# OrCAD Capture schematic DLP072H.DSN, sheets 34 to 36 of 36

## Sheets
34 PAGE13 - Controller VIDEO I/F: size A3
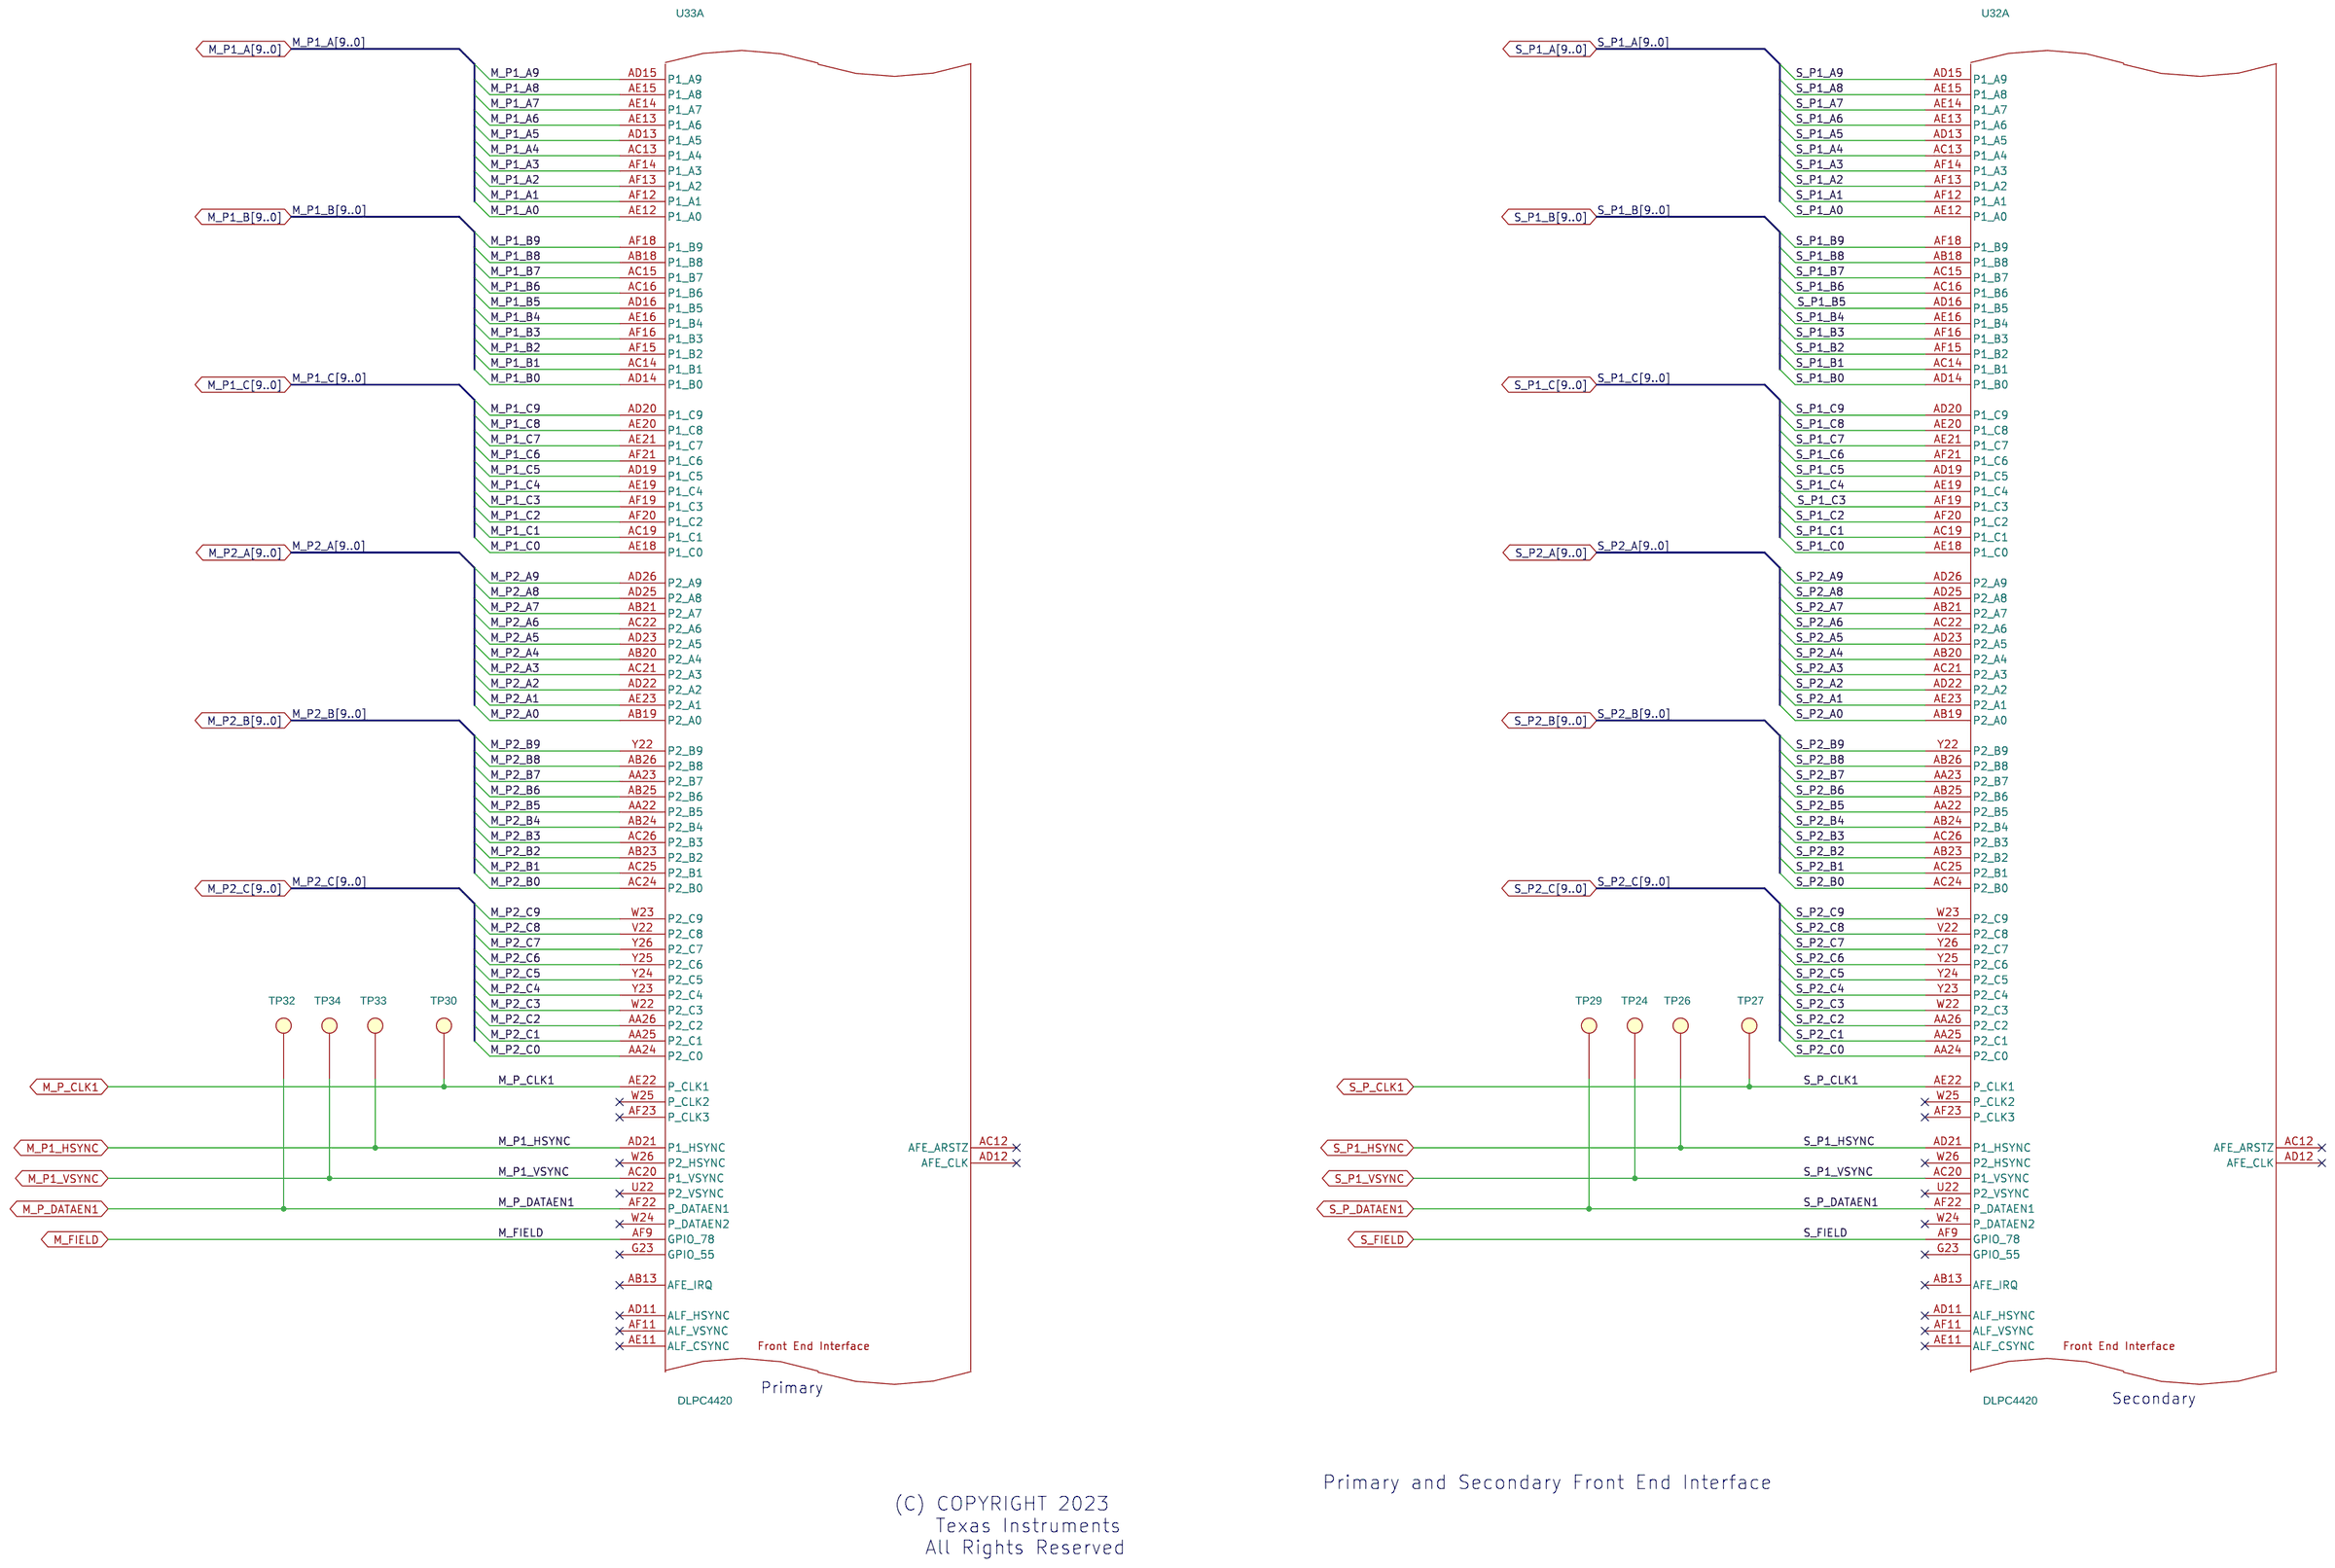
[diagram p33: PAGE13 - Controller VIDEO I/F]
35 PAGE22 - GPIOX, KEYPD I/F, IR: size A3
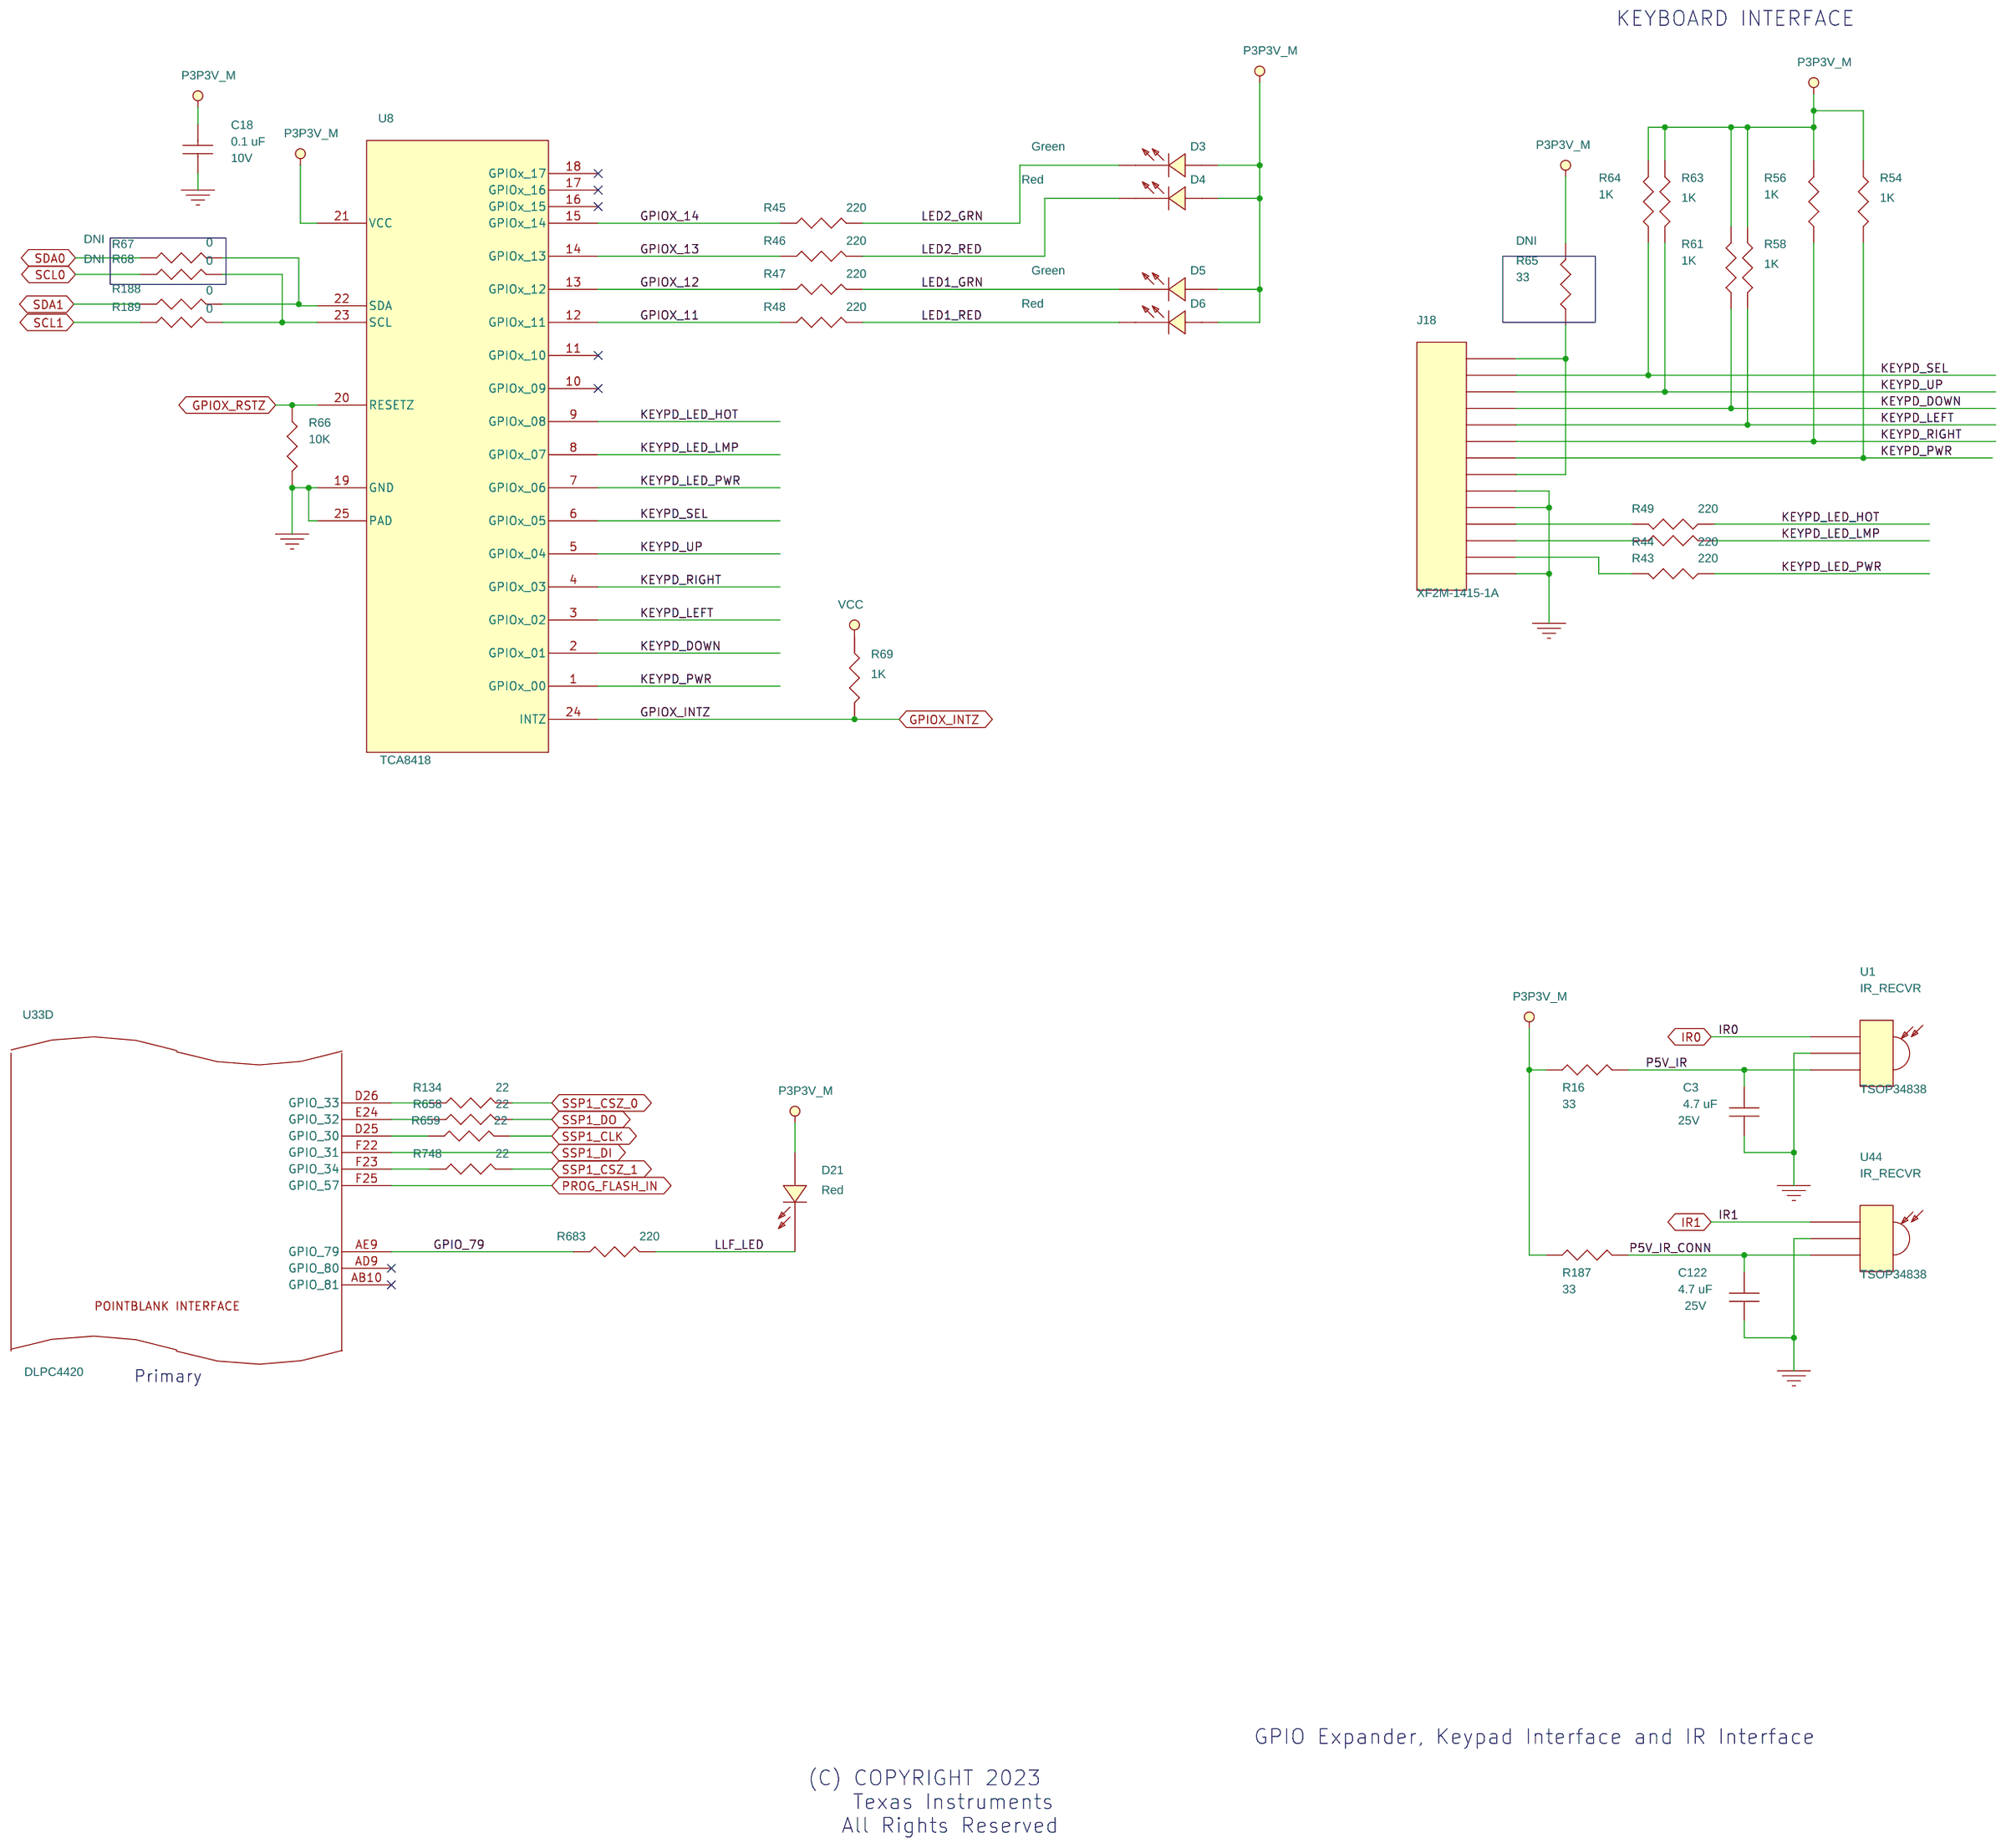
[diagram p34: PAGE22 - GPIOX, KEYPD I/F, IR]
36 PAGE15 - SECONDARY DMD FLEX I/F: size A3
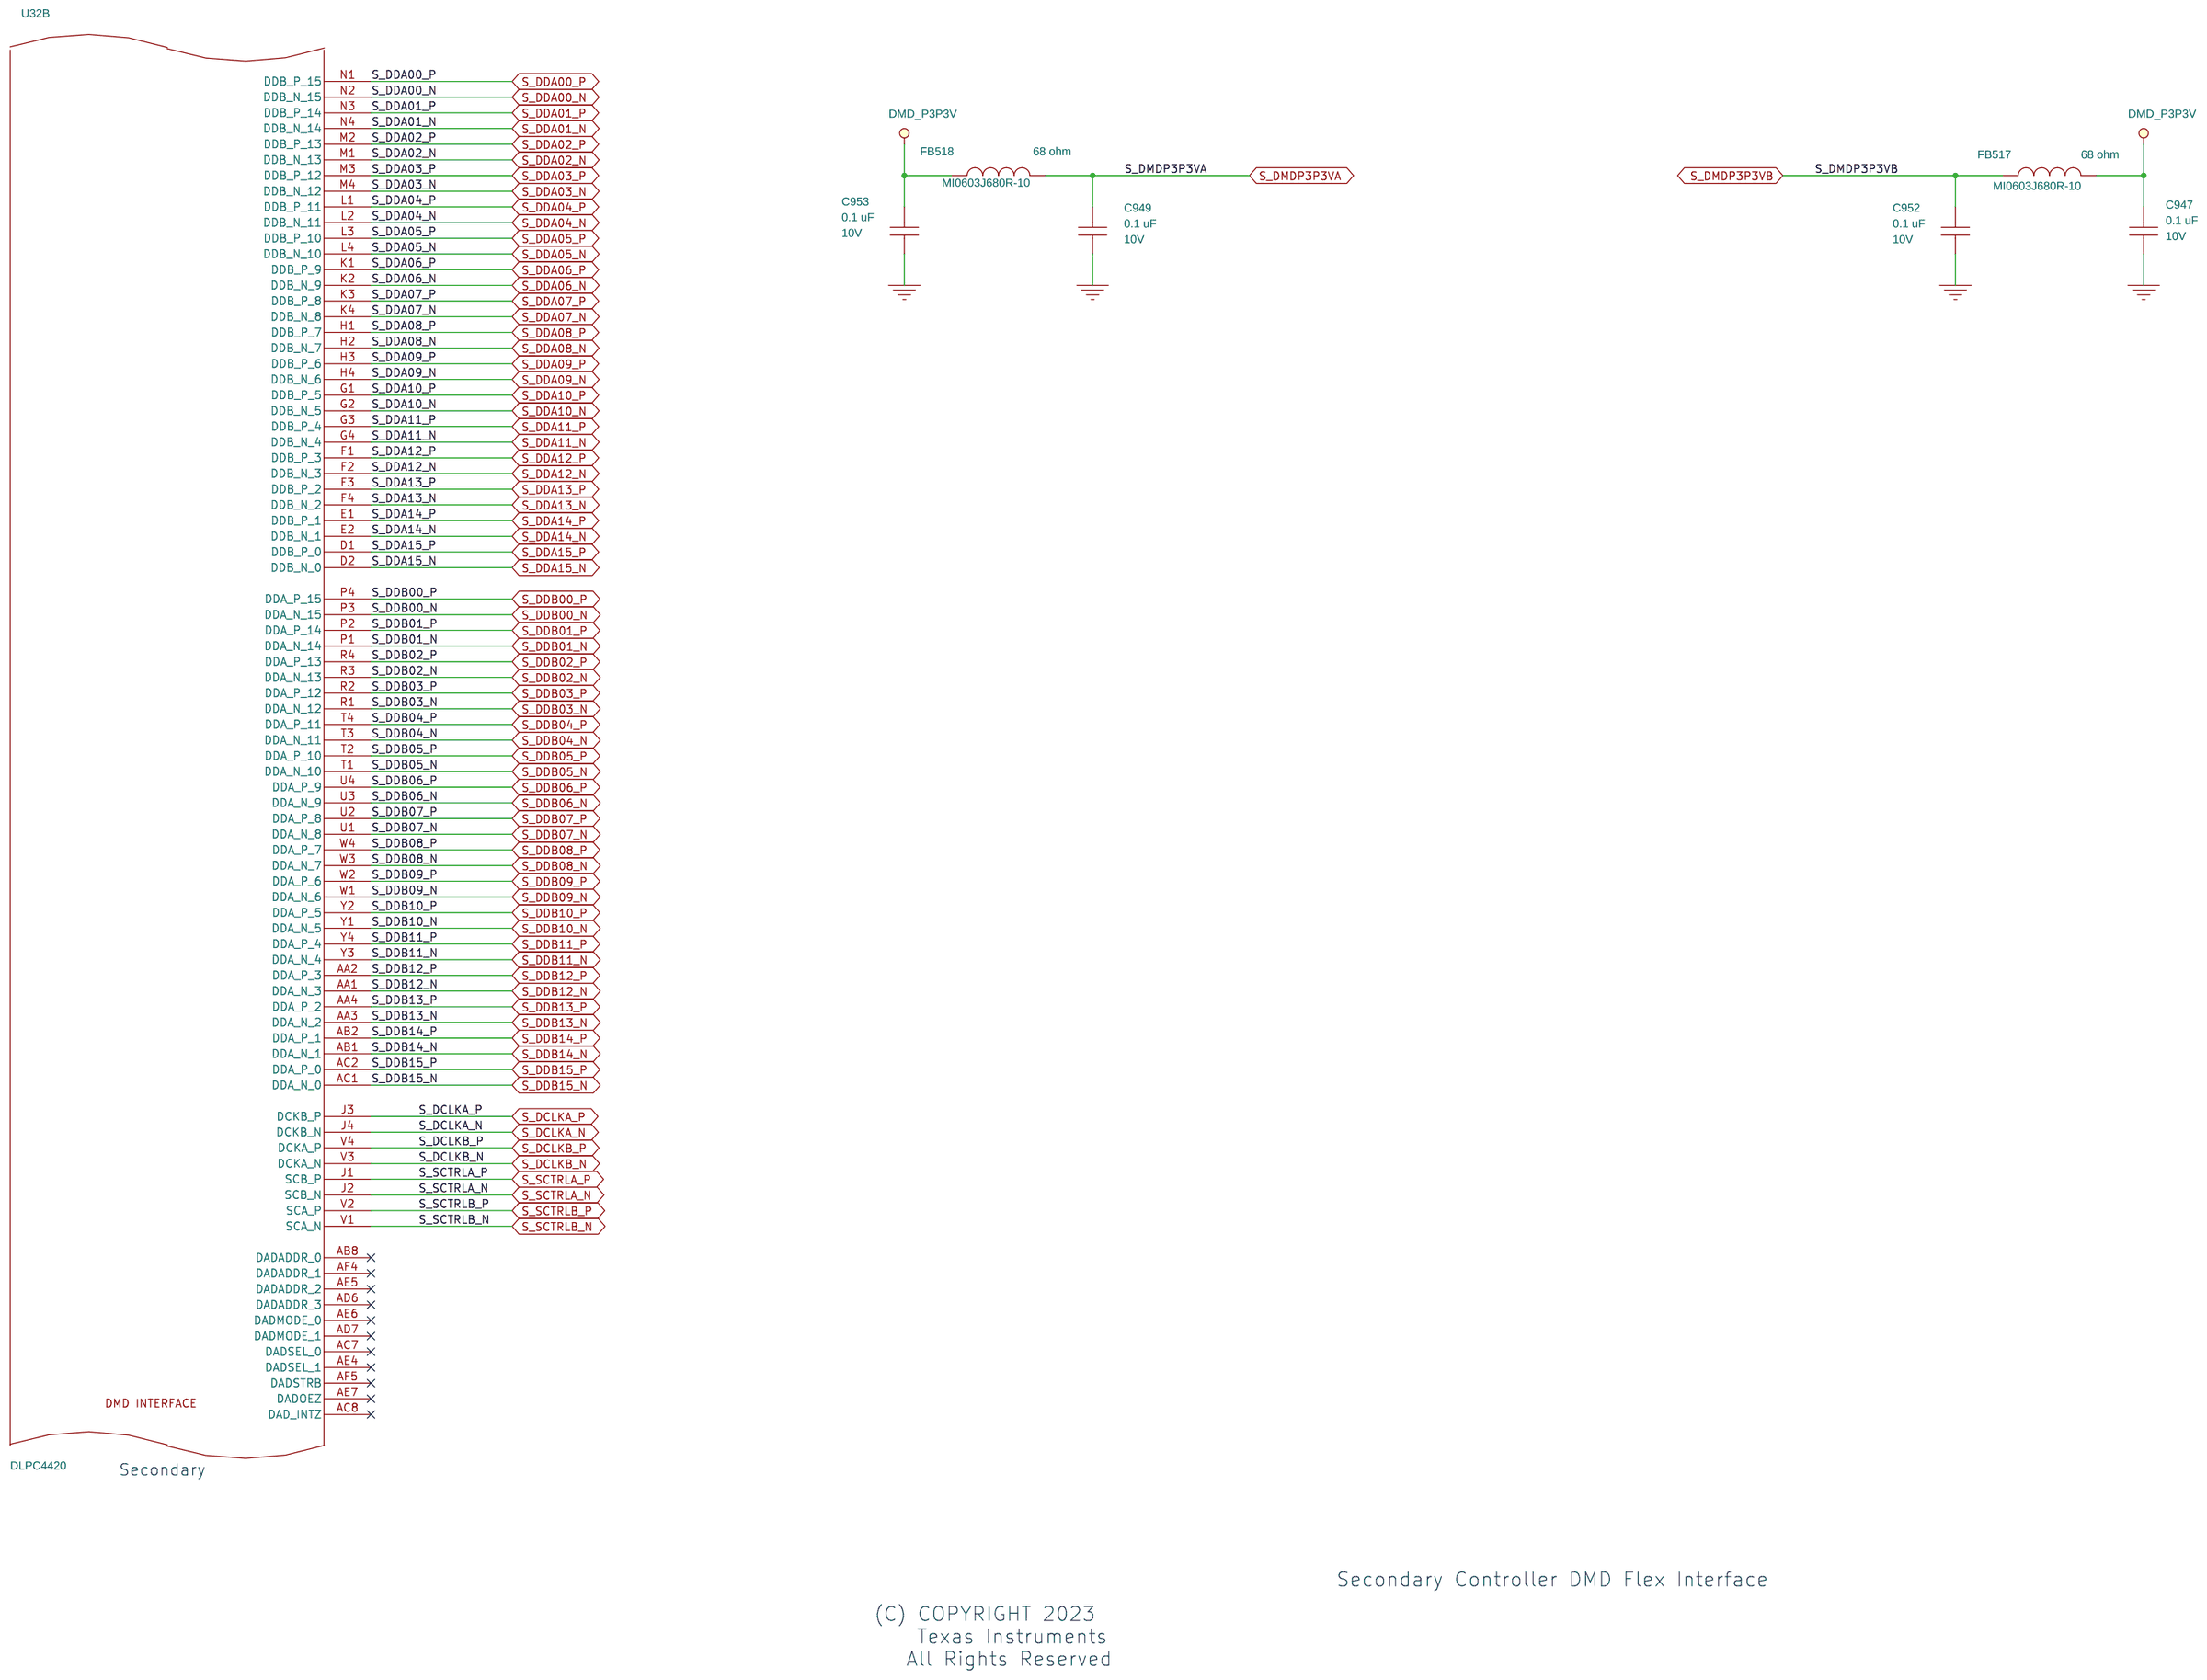
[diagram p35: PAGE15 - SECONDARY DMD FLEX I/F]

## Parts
sheet PAGE13 - Controller VIDEO I/F
TP24  Testpoint  [TP]
TP26  Testpoint  [TP]
TP27  Testpoint  [TP]
TP29  Testpoint  [TP]
TP30  Testpoint  [TP]
TP32  Testpoint  [TP]
TP33  Testpoint  [TP]
TP34  Testpoint  [TP]
sheet PAGE15 - SECONDARY DMD FLEX I/F
C947  0.1 uF  [CAP_0402]
C949  0.1 uF  [CAP_0402]
C952  0.1 uF  [CAP_0402]
C953  0.1 uF  [CAP_0402]
FB517  68 ohm  [FLTR_0603]
FB518  68 ohm  [FLTR_0603]
sheet PAGE16 - INPUT PWR & PMD1000
U32  DLPC4420  [BGA552-DDP4422_TI]  (sections A,B,C,D,E,F,G,H,I,J)
U33  DLPC4420  [BGA552-DDP4422_TI]  (sections A,B,C,D,E,F,G,H,I,J)
sheet PAGE22 - GPIOX, KEYPD I/F, IR
C3  4.7 uF  [CAP_0805]
C18  0.1 uF  [CAP_0402]
C122  4.7 uF  [CAP_0805]
D3  Green  [D_0603]
D4  Red  [D_0603]
D5  Green  [D_0603]
D6  Red  [D_0603]
D21  Red  [D_0603]
J18  CON14  [CONN14-XF2M_OMRON]
R16  33  [RES_0402]
R43  220  [RES_0603]
R44  220  [RES_0603]
R45  220  [RES_0603]
R46  220  [RES_0603]
R47  220  [RES_0603]
R48  220  [RES_0603]
R49  220  [RES_0603]
R54  1K  [RES_0402]
R56  1K  [RES_0402]
R58  1K  [RES_0402]
R61  1K  [RES_0402]
R63  1K  [RES_0402]
R64  1K  [RES_0402]
R65  33  [RES_0402]
R66  10K  [RES_0402]
R67  0  [RES_0402]
R68  0  [RES_0402]
R69  1K  [RES_0402]
R134  22  [RES_0402]
R187  33  [RES_0402]
R188  0  [RES_0402]
R189  0  [RES_0402]
R658  22  [RES_0402]
R659  22  [RES_0402]
R683  220  [RES_0603]
R748  22  [RES_0402]
U1  IR_RECVR  [VISHAY_IR_TSOP348]
U8  TCA8418  [24QFN_TI]
U44  IR_RECVR  [VISHAY_IR_TSOP348]

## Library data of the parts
TP24 TP26 TP27 TP29 TP30 TP32-TP34 = Testpoint: Test point
C18 C947 C949 C952 C953 = CAP_NP: Capacitor; CCA: 34; MFG: KEMET; Part Number: C0402C104K8RACTU; RATING: 10V; SOURCE: DIGI 399-3520-1-ND; TOLERANCE: 10%; Type: X7R
FB517 FB518 = INDUCTOR: Ferrite; CCA: 132; ICA_MFR_NAME: STEWARD; ICA_PARTNUM: $$731362$$MI0603J680R-10; MFG: STEWARD; Part Number: MI0603J680R-10; RATING: 1A, 100MHz; SOURCE: DIGI 240-2372-1-ND
U32 U33 = DDP442x: IC, ASIC; CCA: 54; MFG: TI; Part Number: DLPC4420ZPC; SOURCE: PROVIDED BY TI
C3 C122 = CAP_NP: Capacitor; CCA: 42; MFG: TDK; Part Number: C2012X7R1E475K125AB; RATING: 25V; SOURCE: DIGI 445-5972-1-ND; TOLERANCE: 10%; Type: X7R
D3 D5 = LED_GREEN_CLEAR_0603: LED; Part Number: LTST-C190GKT
D4 D6 D21 = LED_GREEN_CLEAR_0603: LED; MFG Part Number: LTST-C191KRKT; Part Number: LTST-C191KRKT
J18 = CON14: Connector, 14 pin, ribbon; CCA: 177; MFG: OMRON; Part Number: XF2M-1415-1A; SOURCE: DIGI OR755CT-ND
R16 R187 = R: Resistor; CCA: 67; ICA_MFR_NAME: PANASONIC; ICA_PARTNUM: $$1785048$$ERJ-3GSYJ102; MFG: PANASONIC; Part Number: ERJ-2GEJ330X; RATING: 1/10W; SOURCE: DIGI P33JCT-ND; TOLERANCE: 5%
R43-R49 R683 = R: Resistor; CCA: 95; ICA_MFR_NAME: PANASONIC; ICA_PARTNUM: $$1785048$$ERJ-3GSYJ102; MFG: PANASONIC; Part Number: ERJ-3GEYJ221V; RATING: 1/10W; SOURCE: DIGI P220GCT-ND; TOLERANCE: 5%
R54 R56 R58 R61 R63 R64 R69 = R: Resistor; CCA: 64; ICA_MFR_NAME: PANASONIC; ICA_PARTNUM: $$1785048$$ERJ-3GSYJ102; MFG: PANASONIC; Part Number: ERJ-2GEJ102X; RATING: 1/10W; SOURCE: DIGI P1.0KJCT-ND; TOLERANCE: 5%
R65 = R: Resistor; CCA: 67; DNI: DNI; ICA_MFR_NAME: PANASONIC; ICA_PARTNUM: $$1785048$$ERJ-3GSYJ102; MFG: PANASONIC; Part Number: ERJ-2GEJ330X; RATING: 1/10W; SOURCE: DIGI P33JCT-ND; TOLERANCE: 5%
R66 = R: Resistor; CCA: 65; ICA_MFR_NAME: PANASONIC; ICA_PARTNUM: $$1785048$$ERJ-3GSYJ102; MFG: PANASONIC; Part Number: ERJ-2GEJ103X; RATING: 1/10W; SOURCE: DIGI P10.0KLCT-ND; TOLERANCE: 5%
R67 R68 = R: Resistor; CCA: 62; DNI: DNI; ICA_MFR_NAME: PANASONIC; ICA_PARTNUM: $$1785048$$ERJ-3GSYJ102; MFG: PANASONIC; Part Number: ERJ-2GE0R00X; RATING: 1/10W; SOURCE: DIGI P0.0JCT-ND
R134 R658 R659 R748 = R: Resistor; CCA: 143; MFG: YAGEO; Part Number: RC0402FR-0722RL; RATING: 1/16W; SOURCE: DIGI 311-22.0LRTR-ND; TOLERANCE: 1%
R188 R189 = R: Resistor; CCA: 62; ICA_MFR_NAME: PANASONIC; ICA_PARTNUM: $$1785048$$ERJ-3GSYJ102; MFG: PANASONIC; Part Number: ERJ-2GE0R00X; RATING: 1/10W; SOURCE: DIGI P0.0JCT-ND
U1 U44 = IR_RECVR: IC, IR Receiver; CCA: 175; MFG: VISHAY; Part Number: TSOP34838; SOURCE: VISHAY
U8 = TCA8418_0: IC, GPIO Expander; CCA: 160; MFG: TI; Part Number: TCA8418RTWR; SOURCE: DIGI 296-25223-1-ND

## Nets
GND: C3.1 C18.1 C122.1 C947.1 C949.1 C952.1 C953.1 J18.9 J18.10 J18.14 R66.2 U1.2 U8.19(GND) U8.25(PAD) U44.2 ; also on sheet 2 5 6 7 8 9 10 11 12 13 14 15 16 17 18 19 20 21 22 23 24 25 26 27 28 30 31 32 33
P5V_IR: C3.2 R16.1 U1.3
P5V_IR_CONN: C122.2 R187.1 U44.3
DMD_P3P3V: C947.2 C953.2 FB517.1 FB518.1 ; also on sheet 11 14
GPIO_79: R683.1 U33.AE9(GPIO_79)
GPIOX_11: R48.1 U8.12(GPIOx_11)
GPIOX_12: R47.1 U8.13(GPIOx_12)
GPIOX_13: R46.1 U8.14(GPIOx_13)
GPIOX_14: R45.1 U8.15(GPIOx_14)
GPIOX_INTZ: R69.1 U8.24(INTZ) ; also on sheet 17
GPIOX_RSTZ: R66.1 U8.20(RESETZ) ; also on sheet 17
IR0: U1.1 ; also on sheet 17
IR1: U44.1 ; also on sheet 17
KEYPD_DOWN: J18.4 R61.1 U8.2(GPIOx_01)
KEYPD_LED_HOT: R49.2 U8.9(GPIOx_08)
KEYPD_LED_LMP: R44.2 U8.8(GPIOx_07)
KEYPD_LED_PWR: R43.2 U8.7(GPIOx_06)
KEYPD_LEFT: J18.5 R58.1 U8.3(GPIOx_02)
KEYPD_PWR: J18.7 R54.1 U8.1(GPIOx_00)
KEYPD_RIGHT: J18.6 R56.1 U8.4(GPIOx_03)
KEYPD_SEL: J18.2 R64.1 U8.6(GPIOx_05)
KEYPD_UP: J18.3 R63.1 U8.5(GPIOx_04)
LED1_GRN: D5.1(CATHODE) R47.2
LED1_RED: D6.1(CATHODE) R48.2
LED2_GRN: D3.1(CATHODE) R45.2
LED2_RED: D4.1(CATHODE) R46.2
LLF_LED: D21.1(CATHODE) R683.2
M_FIELD: U33.AF9(GPIO_78) ; also on sheet 31
M_P1_A0: U33.AE12(P1_A0) ; also on sheet 31
M_P1_A1: U33.AF12(P1_A1) ; also on sheet 31
M_P1_A2: U33.AF13(P1_A2) ; also on sheet 31
M_P1_A3: U33.AF14(P1_A3) ; also on sheet 31
M_P1_A4: U33.AC13(P1_A4) ; also on sheet 31
M_P1_A5: U33.AD13(P1_A5) ; also on sheet 31
M_P1_A6: U33.AE13(P1_A6) ; also on sheet 31
M_P1_A7: U33.AE14(P1_A7) ; also on sheet 31
M_P1_A8: U33.AE15(P1_A8) ; also on sheet 31
M_P1_A9: U33.AD15(P1_A9) ; also on sheet 31
M_P1_B0: U33.AD14(P1_B0) ; also on sheet 31
M_P1_B1: U33.AC14(P1_B1) ; also on sheet 31
M_P1_B2: U33.AF15(P1_B2) ; also on sheet 31
M_P1_B3: U33.AF16(P1_B3) ; also on sheet 31
M_P1_B4: U33.AE16(P1_B4) ; also on sheet 31
M_P1_B5: U33.AD16(P1_B5) ; also on sheet 31
M_P1_B6: U33.AC16(P1_B6) ; also on sheet 31
M_P1_B7: U33.AC15(P1_B7) ; also on sheet 31
M_P1_B8: U33.AB18(P1_B8) ; also on sheet 31
M_P1_B9: U33.AF18(P1_B9) ; also on sheet 31
M_P1_C0: U33.AE18(P1_C0) ; also on sheet 31
M_P1_C1: U33.AC19(P1_C1) ; also on sheet 31
M_P1_C2: U33.AF20(P1_C2) ; also on sheet 31
M_P1_C3: U33.AF19(P1_C3) ; also on sheet 31
M_P1_C4: U33.AE19(P1_C4) ; also on sheet 31
M_P1_C5: U33.AD19(P1_C5) ; also on sheet 31
M_P1_C6: U33.AF21(P1_C6) ; also on sheet 31
M_P1_C7: U33.AE21(P1_C7) ; also on sheet 31
M_P1_C8: U33.AE20(P1_C8) ; also on sheet 31
M_P1_C9: U33.AD20(P1_C9) ; also on sheet 31
M_P1_HSYNC: TP33.1 U33.AD21(P1_HSYNC) ; also on sheet 31
M_P1_VSYNC: TP34.1 U33.AC20(P1_VSYNC) ; also on sheet 31
M_P2_A0: U33.AB19(P2_A0) ; also on sheet 31
M_P2_A1: U33.AE23(P2_A1) ; also on sheet 31
M_P2_A2: U33.AD22(P2_A2) ; also on sheet 31
M_P2_A3: U33.AC21(P2_A3) ; also on sheet 31
M_P2_A4: U33.AB20(P2_A4) ; also on sheet 31
M_P2_A5: U33.AD23(P2_A5) ; also on sheet 31
M_P2_A6: U33.AC22(P2_A6) ; also on sheet 31
M_P2_A7: U33.AB21(P2_A7) ; also on sheet 31
M_P2_A8: U33.AD25(P2_A8) ; also on sheet 31
M_P2_A9: U33.AD26(P2_A9) ; also on sheet 31
M_P2_B0: U33.AC24(P2_B0) ; also on sheet 31
M_P2_B1: U33.AC25(P2_B1) ; also on sheet 31
M_P2_B2: U33.AB23(P2_B2) ; also on sheet 31
M_P2_B3: U33.AC26(P2_B3) ; also on sheet 31
M_P2_B4: U33.AB24(P2_B4) ; also on sheet 31
M_P2_B5: U33.AA22(P2_B5) ; also on sheet 31
M_P2_B6: U33.AB25(P2_B6) ; also on sheet 31
M_P2_B7: U33.AA23(P2_B7) ; also on sheet 31
M_P2_B8: U33.AB26(P2_B8) ; also on sheet 31
M_P2_B9: U33.Y22(P2_B9) ; also on sheet 31
M_P2_C0: U33.AA24(P2_C0) ; also on sheet 31
M_P2_C1: U33.AA25(P2_C1) ; also on sheet 31
M_P2_C2: U33.AA26(P2_C2) ; also on sheet 31
M_P2_C3: U33.W22(P2_C3) ; also on sheet 31
M_P2_C4: U33.Y23(P2_C4) ; also on sheet 31
M_P2_C5: U33.Y24(P2_C5) ; also on sheet 31
M_P2_C6: U33.Y25(P2_C6) ; also on sheet 31
M_P2_C7: U33.Y26(P2_C7) ; also on sheet 31
M_P2_C8: U33.V22(P2_C8) ; also on sheet 31
M_P2_C9: U33.W23(P2_C9) ; also on sheet 31
M_P_CLK1: TP30.1 U33.AE22(P_CLK1) ; also on sheet 31
M_P_DATAEN1: TP32.1 U33.AF22(P_DATAEN1) ; also on sheet 31
P3P3V_M: C18.2 D3.2(ANODE) D4.2(ANODE) D5.2(ANODE) D6.2(ANODE) D21.2(ANODE) R16.2 R54.2 R56.2 R58.2 R61.2 R63.2 R64.2 R65.2 R69.2 R187.2 U8.21(VCC) ; also on sheet 12 13 14 15 16 17 18 20 21 23 24 27 30
PROG_FLASH_IN: U33.F25(GPIO_57) ; also on sheet 33
S_DCLKA_N: U32.J4(DCKB_N) ; also on sheet 2
S_DCLKA_P: U32.J3(DCKB_P) ; also on sheet 2
S_DCLKB_N: U32.V3(DCKA_N) ; also on sheet 2
S_DCLKB_P: U32.V4(DCKA_P) ; also on sheet 2
S_DDA00_N: U32.N2(DDB_N_15) ; also on sheet 2
S_DDA00_P: U32.N1(DDB_P_15) ; also on sheet 2
S_DDA01_N: U32.N4(DDB_N_14) ; also on sheet 2
S_DDA01_P: U32.N3(DDB_P_14) ; also on sheet 2
S_DDA02_N: U32.M1(DDB_N_13) ; also on sheet 2
S_DDA02_P: U32.M2(DDB_P_13) ; also on sheet 2
S_DDA03_N: U32.M4(DDB_N_12) ; also on sheet 2
S_DDA03_P: U32.M3(DDB_P_12) ; also on sheet 2
S_DDA04_N: U32.L2(DDB_N_11) ; also on sheet 2
S_DDA04_P: U32.L1(DDB_P_11) ; also on sheet 2
S_DDA05_N: U32.L4(DDB_N_10) ; also on sheet 2
S_DDA05_P: U32.L3(DDB_P_10) ; also on sheet 2
S_DDA06_N: U32.K2(DDB_N_9) ; also on sheet 2
S_DDA06_P: U32.K1(DDB_P_9) ; also on sheet 2
S_DDA07_N: U32.K4(DDB_N_8) ; also on sheet 2
S_DDA07_P: U32.K3(DDB_P_8) ; also on sheet 2
S_DDA08_N: U32.H2(DDB_N_7) ; also on sheet 2
S_DDA08_P: U32.H1(DDB_P_7) ; also on sheet 2
S_DDA09_N: U32.H4(DDB_N_6) ; also on sheet 2
S_DDA09_P: U32.H3(DDB_P_6) ; also on sheet 2
S_DDA10_N: U32.G2(DDB_N_5) ; also on sheet 2
S_DDA10_P: U32.G1(DDB_P_5) ; also on sheet 2
S_DDA11_N: U32.G4(DDB_N_4) ; also on sheet 2
S_DDA11_P: U32.G3(DDB_P_4) ; also on sheet 2
S_DDA12_N: U32.F2(DDB_N_3) ; also on sheet 2
S_DDA12_P: U32.F1(DDB_P_3) ; also on sheet 2
S_DDA13_N: U32.F4(DDB_N_2) ; also on sheet 2
S_DDA13_P: U32.F3(DDB_P_2) ; also on sheet 2
S_DDA14_N: U32.E2(DDB_N_1) ; also on sheet 2
S_DDA14_P: U32.E1(DDB_P_1) ; also on sheet 2
S_DDA15_N: U32.D2(DDB_N_0) ; also on sheet 2
S_DDA15_P: U32.D1(DDB_P_0) ; also on sheet 2
S_DDB00_N: U32.P3(DDA_N_15) ; also on sheet 2
S_DDB00_P: U32.P4(DDA_P_15) ; also on sheet 2
S_DDB01_N: U32.P1(DDA_N_14) ; also on sheet 2
S_DDB01_P: U32.P2(DDA_P_14) ; also on sheet 2
S_DDB02_N: U32.R3(DDA_N_13) ; also on sheet 2
S_DDB02_P: U32.R4(DDA_P_13) ; also on sheet 2
S_DDB03_N: U32.R1(DDA_N_12) ; also on sheet 2
S_DDB03_P: U32.R2(DDA_P_12) ; also on sheet 2
S_DDB04_N: U32.T3(DDA_N_11) ; also on sheet 2
S_DDB04_P: U32.T4(DDA_P_11) ; also on sheet 2
S_DDB05_N: U32.T1(DDA_N_10) ; also on sheet 2
S_DDB05_P: U32.T2(DDA_P_10) ; also on sheet 2
S_DDB06_N: U32.U3(DDA_N_9) ; also on sheet 2
S_DDB06_P: U32.U4(DDA_P_9) ; also on sheet 2
S_DDB07_N: U32.U1(DDA_N_8) ; also on sheet 2
S_DDB07_P: U32.U2(DDA_P_8) ; also on sheet 2
S_DDB08_N: U32.W3(DDA_N_7) ; also on sheet 2
S_DDB08_P: U32.W4(DDA_P_7) ; also on sheet 2
S_DDB09_N: U32.W1(DDA_N_6) ; also on sheet 2
S_DDB09_P: U32.W2(DDA_P_6) ; also on sheet 2
S_DDB10_N: U32.Y1(DDA_N_5) ; also on sheet 2
S_DDB10_P: U32.Y2(DDA_P_5) ; also on sheet 2
S_DDB11_N: U32.Y3(DDA_N_4) ; also on sheet 2
S_DDB11_P: U32.Y4(DDA_P_4) ; also on sheet 2
S_DDB12_N: U32.AA1(DDA_N_3) ; also on sheet 2
S_DDB12_P: U32.AA2(DDA_P_3) ; also on sheet 2
S_DDB13_N: U32.AA3(DDA_N_2) ; also on sheet 2
S_DDB13_P: U32.AA4(DDA_P_2) ; also on sheet 2
S_DDB14_N: U32.AB1(DDA_N_1) ; also on sheet 2
S_DDB14_P: U32.AB2(DDA_P_1) ; also on sheet 2
S_DDB15_N: U32.AC1(DDA_N_0) ; also on sheet 2
S_DDB15_P: U32.AC2(DDA_P_0) ; also on sheet 2
S_DMDP3P3VA: C949.2 FB518.2 ; also on sheet 2
S_DMDP3P3VB: C952.2 FB517.2 ; also on sheet 2
S_FIELD: U32.AF9(GPIO_78) ; also on sheet 31
S_P1_A0: U32.AE12(P1_A0) ; also on sheet 31
S_P1_A1: U32.AF12(P1_A1) ; also on sheet 31
S_P1_A2: U32.AF13(P1_A2) ; also on sheet 31
S_P1_A3: U32.AF14(P1_A3) ; also on sheet 31
S_P1_A4: U32.AC13(P1_A4) ; also on sheet 31
S_P1_A5: U32.AD13(P1_A5) ; also on sheet 31
S_P1_A6: U32.AE13(P1_A6) ; also on sheet 31
S_P1_A7: U32.AE14(P1_A7) ; also on sheet 31
S_P1_A8: U32.AE15(P1_A8) ; also on sheet 31
S_P1_A9: U32.AD15(P1_A9) ; also on sheet 31
S_P1_B0: U32.AD14(P1_B0) ; also on sheet 31
S_P1_B1: U32.AC14(P1_B1) ; also on sheet 31
S_P1_B2: U32.AF15(P1_B2) ; also on sheet 31
S_P1_B3: U32.AF16(P1_B3) ; also on sheet 31
S_P1_B4: U32.AE16(P1_B4) ; also on sheet 31
S_P1_B5: U32.AD16(P1_B5) ; also on sheet 31
S_P1_B6: U32.AC16(P1_B6) ; also on sheet 31
S_P1_B7: U32.AC15(P1_B7) ; also on sheet 31
S_P1_B8: U32.AB18(P1_B8) ; also on sheet 31
S_P1_B9: U32.AF18(P1_B9) ; also on sheet 31
S_P1_C0: U32.AE18(P1_C0) ; also on sheet 31
S_P1_C1: U32.AC19(P1_C1) ; also on sheet 31
S_P1_C2: U32.AF20(P1_C2) ; also on sheet 31
S_P1_C3: U32.AF19(P1_C3) ; also on sheet 31
S_P1_C4: U32.AE19(P1_C4) ; also on sheet 31
S_P1_C5: U32.AD19(P1_C5) ; also on sheet 31
S_P1_C6: U32.AF21(P1_C6) ; also on sheet 31
S_P1_C7: U32.AE21(P1_C7) ; also on sheet 31
S_P1_C8: U32.AE20(P1_C8) ; also on sheet 31
S_P1_C9: U32.AD20(P1_C9) ; also on sheet 31
S_P1_HSYNC: TP26.1 U32.AD21(P1_HSYNC) ; also on sheet 31
S_P1_VSYNC: TP24.1 U32.AC20(P1_VSYNC) ; also on sheet 31
S_P2_A0: U32.AB19(P2_A0) ; also on sheet 31
S_P2_A1: U32.AE23(P2_A1) ; also on sheet 31
S_P2_A2: U32.AD22(P2_A2) ; also on sheet 31
S_P2_A3: U32.AC21(P2_A3) ; also on sheet 31
S_P2_A4: U32.AB20(P2_A4) ; also on sheet 31
S_P2_A5: U32.AD23(P2_A5) ; also on sheet 31
S_P2_A6: U32.AC22(P2_A6) ; also on sheet 31
S_P2_A7: U32.AB21(P2_A7) ; also on sheet 31
S_P2_A8: U32.AD25(P2_A8) ; also on sheet 31
S_P2_A9: U32.AD26(P2_A9) ; also on sheet 31
S_P2_B0: U32.AC24(P2_B0) ; also on sheet 31
S_P2_B1: U32.AC25(P2_B1) ; also on sheet 31
S_P2_B2: U32.AB23(P2_B2) ; also on sheet 31
S_P2_B3: U32.AC26(P2_B3) ; also on sheet 31
S_P2_B4: U32.AB24(P2_B4) ; also on sheet 31
S_P2_B5: U32.AA22(P2_B5) ; also on sheet 31
S_P2_B6: U32.AB25(P2_B6) ; also on sheet 31
S_P2_B7: U32.AA23(P2_B7) ; also on sheet 31
S_P2_B8: U32.AB26(P2_B8) ; also on sheet 31
S_P2_B9: U32.Y22(P2_B9) ; also on sheet 31
S_P2_C0: U32.AA24(P2_C0) ; also on sheet 31
S_P2_C1: U32.AA25(P2_C1) ; also on sheet 31
S_P2_C2: U32.AA26(P2_C2) ; also on sheet 31
S_P2_C3: U32.W22(P2_C3) ; also on sheet 31
S_P2_C4: U32.Y23(P2_C4) ; also on sheet 31
S_P2_C5: U32.Y24(P2_C5) ; also on sheet 31
S_P2_C6: U32.Y25(P2_C6) ; also on sheet 31
S_P2_C7: U32.Y26(P2_C7) ; also on sheet 31
S_P2_C8: U32.V22(P2_C8) ; also on sheet 31
S_P2_C9: U32.W23(P2_C9) ; also on sheet 31
S_P_CLK1: TP27.1 U32.AE22(P_CLK1) ; also on sheet 31
S_P_DATAEN1: TP29.1 U32.AF22(P_DATAEN1) ; also on sheet 31
S_SCTRLA_N: U32.J2(SCB_N) ; also on sheet 2
S_SCTRLA_P: U32.J1(SCB_P) ; also on sheet 2
S_SCTRLB_N: U32.V1(SCA_N) ; also on sheet 2
S_SCTRLB_P: U32.V2(SCA_P) ; also on sheet 2
SCL0: R68.1 ; also on sheet 17 30
SCL1: R189.1 ; also on sheet 16 17 25 30 33
SDA0: R67.1 ; also on sheet 17 30
SDA1: R188.1 ; also on sheet 16 17 25 30 33
SSP1_CLK: R659.2 ; also on sheet 33
SSP1_CSZ_0: R134.2 ; also on sheet 33
SSP1_CSZ_1: R748.2 ; also on sheet 33
SSP1_DI: U33.F22(GPIO_31) ; also on sheet 33
SSP1_DO: R658.2 ; also on sheet 33
N18767865: R67.2 R188.2 U8.22(SDA)
N18768240: J18.1 J18.8 R65.1
N18768252: J18.13 R43.1
N18768258: J18.11 R49.1
N18768267: J18.12 R44.1
N18851658: R134.1 U33.D26(GPIO_33)
N18851665: R658.1 U33.E24(GPIO_32)
N18851672: R659.1 U33.D25(GPIO_30)
N19259828: R68.2 R189.2 U8.23(SCL)
N19802127: R748.1 U33.F23(GPIO_34)

Not connected (* = marked no-connect by the designer): U8 10(GPIOx_09)* 11(GPIOx_10)* 16(GPIOx_15)* 17(GPIOx_16)* 18(GPIOx_17)*; U32 AB8(DADADDR_0)* AB13(AFE_IRQ)* AC7(DADSEL_0)* AC8(DAD_INTZ)* AC12(AFE_ARSTZ)* AD6(DADADDR_3)* AD7(DADMODE_1)* AD11(ALF_HSYNC)* AD12(AFE_CLK)* AE4(DADSEL_1)* AE5(DADADDR_2)* AE6(DADMODE_0)* AE7(DADOEZ)* AE11(ALF_CSYNC)* AF4(DADADDR_1)* AF5(DADSTRB)* AF11(ALF_VSYNC)* AF23(P_CLK3)* G23(GPIO_55)* U22(P2_VSYNC)* W24(P_DATAEN2)* W25(P_CLK2)* W26(P2_HSYNC)*; U33 AB10(GPIO_81)* AB13(AFE_IRQ)* AC12(AFE_ARSTZ)* AD9(GPIO_80)* AD11(ALF_HSYNC)* AD12(AFE_CLK)* AE11(ALF_CSYNC)* AF11(ALF_VSYNC)* AF23(P_CLK3)* G23(GPIO_55)* U22(P2_VSYNC)* W24(P_DATAEN2)* W25(P_CLK2)* W26(P2_HSYNC)*

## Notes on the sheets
sheet 34
- Primary
- Secondary
- Primary and Secondary Front End Interface
- (C) COPYRIGHT 2023
         Texas Instruments
        All Rights Reserved
sheet 35
- KEYBOARD INTERFACE
- Primary
- GPIO Expander, Keypad Interface and IR Interface
- (C) COPYRIGHT 2023
         Texas Instruments
        All Rights Reserved
sheet 36
- Secondary
- Secondary Controller DMD Flex Interface
- (C) COPYRIGHT 2023
         Texas Instruments
        All Rights Reserved
